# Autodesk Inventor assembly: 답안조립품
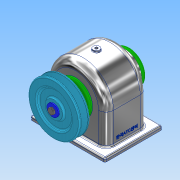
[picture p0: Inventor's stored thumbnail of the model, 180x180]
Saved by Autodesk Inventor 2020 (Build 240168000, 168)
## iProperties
Created: 2022-09
Part Number: 답안조립품
Document SubType Name: Assembly
Designer: user
Author: user
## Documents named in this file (16)
- C:\Users\user\Desktop\답안조립품.iam
- C:\Users\user\Desktop\답안도면.ipt
- C:\Users\user\Desktop\720906V1008\V-벨트풀리.ipt
- C:\Users\user\Desktop\720906V1008\뒤커버.ipt
- C:\Users\user\Desktop\720906V1008\멈춤나사 M4 x 10.ipt
- C:\Users\user\Desktop\720906V1008\베어링 6203.ipt
- C:\Users\user\Desktop\720906V1008\볼트 M3 x 10.ipt
- C:\Users\user\Desktop\720906V1008\스퍼기어.ipt
- C:\Users\user\Desktop\720906V1008\앞커버.ipt
- C:\Users\user\Desktop\720906V1008\오일 실 17 x 30 x 8.ipt
- C:\Users\user\Desktop\720906V1008\와셔 6 x 22.ipt
- C:\Users\user\Desktop\720906V1008\육각머리볼트 M3 x 8.ipt
- C:\Users\user\Desktop\720906V1008\축.ipt
- C:\Users\user\Desktop\720906V1008\칼라.ipt
- C:\Users\user\Desktop\720906V1008\키 5 x 5 x 18.ipt
- C:\Users\user\Desktop\720906V1008\키 6 x 6 x 22.ipt
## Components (9 placed, 2 different names)
1. V-벨트풀리:1
2. ISO 4762 M3 x 10:1
3. ISO 4762 M3 x 10:2
4. ISO 4762 M3 x 10:3
5. ISO 4762 M3 x 10:4
6. ISO 4762 M3 x 10:5
7. ISO 4762 M3 x 10:6
8. ISO 4762 M3 x 10:7
9. ISO 4762 M3 x 10:8
